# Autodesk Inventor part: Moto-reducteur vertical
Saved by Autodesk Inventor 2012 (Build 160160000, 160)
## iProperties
Created: 2013-08
Part Number: Moto-reducteur vertical
Material: Default
Document SubType Name: Modeling
Designer: hilarion
Density: 1 g/cm^3
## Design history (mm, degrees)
node "Moto-reducteur vertical1"
node "Moto-reducteur vertical"
node "Base1"
